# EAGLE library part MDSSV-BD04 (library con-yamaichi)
YAMAICHI CONNECTOR
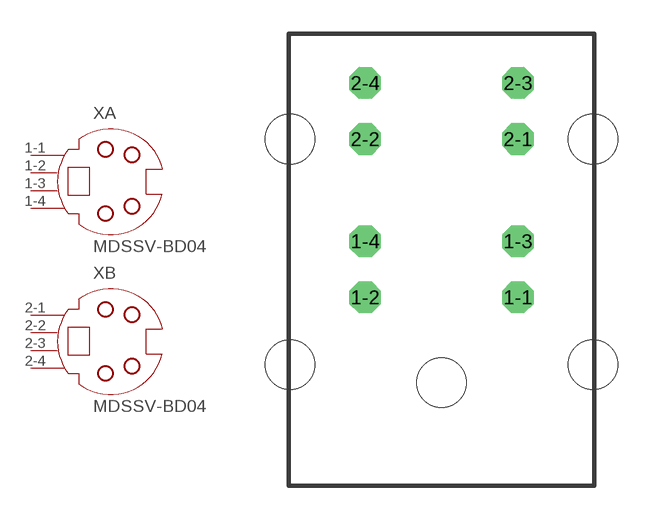
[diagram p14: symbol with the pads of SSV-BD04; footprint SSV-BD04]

Designator prefix X; gates A=SSV-BC04 B=SSV-BC04

## MDSSV-BD04 (OC_FARNELL: unknown; OC_NEWARK: unknown)  [SSV-BD04]
1-1  A:1  pas
1-2  A:2  pas
1-3  A:3  pas
1-4  A:4  pas
2-1  B:1  pas
2-2  B:2  pas
2-3  B:3  pas
2-4  B:4  pas

## Footprint SSV-BD04 (pad centres in mm)
Mini Din YAMAICHI CONNECTOR
drill 0.9 octagon: 1-1 3.4,8.5; 1-2 -3.4,8.5; 1-3 3.4,11; 1-4 -3.4,11; 2-1 3.4,15.55; 2-2 -3.4,15.55; 2-3 3.4,18.05; 2-4 -3.4,18.05
hole 2.2 at -6.75,5.5
hole 2.2 at 0,4.7
hole 2.2 at 6.75,5.5
hole 2.2 at -6.75,15.55
hole 2.2 at 6.75,15.55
